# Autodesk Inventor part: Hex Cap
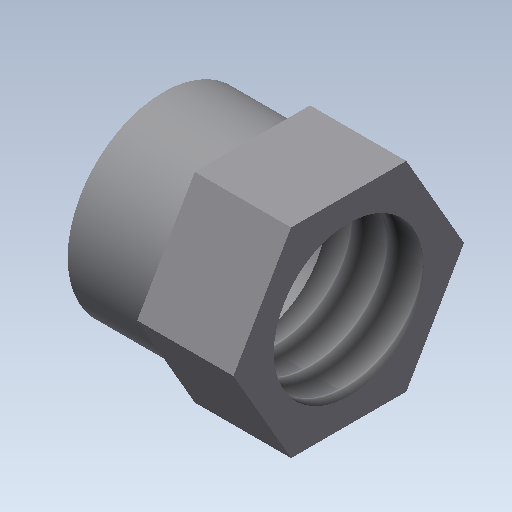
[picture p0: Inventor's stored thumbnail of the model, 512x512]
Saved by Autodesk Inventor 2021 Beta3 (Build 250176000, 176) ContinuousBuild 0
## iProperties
Created: 2012-08
Part Number: Hex Cap
Material: Generic
Document SubType Name: Modeling
Designer: John
Density: 1 g/cm^3
Appearance: Default
Author: John
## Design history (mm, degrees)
sketch "Sketch1"
  geometry: L1 (3.556, -2.053)-(0, -4.106); L2 (0, -4.106)-(-3.556, -2.053); L3 (-3.556, -2.053)-(-3.556, 2.053); L4 (-3.556, 2.053)-(0, 4.106); L5 (0, 4.106)-(3.556, 2.053); L6 (3.556, 2.053)-(3.556, -2.053); 2 further points
  constraints: 12 end point, 1 coincident, 1 vertical, 13 other
  dimensions: "d0" = 7.112 distance between parallel lines of L3 L6
extrude "Extrusion1" new body sketch "Sketch1" distance "d1" = 3.429; taper "d2" = 0 deg
sketch "Sketch2"
  geometry: C1 r 3.404 at (0, 0)
  constraints: 1 centre point
  dimensions: "d3" = 6.8072 diameter of C1
extrude "Extrusion2" join sketch "Sketch2" distance "d4" = 3.175; taper "d5" = 0 deg
sketch "Sketch3"
  geometry: C1 r 3.404 at (0, 0) reference
hole "Hole1" sketch "Sketch3" at (0, 0) diameter "d6" = 5.334; stored, may be unused: countersink angle "d10" = 82 deg, drill point angle "d12" = 118 deg; dims "d7" = 19.05, "d8" = 9.525, "d9" = 6.35, "d11" = 25.4
thread "Thread1" dims "d13" = 3.429, "d14" = 3.175
body "Solid1"
